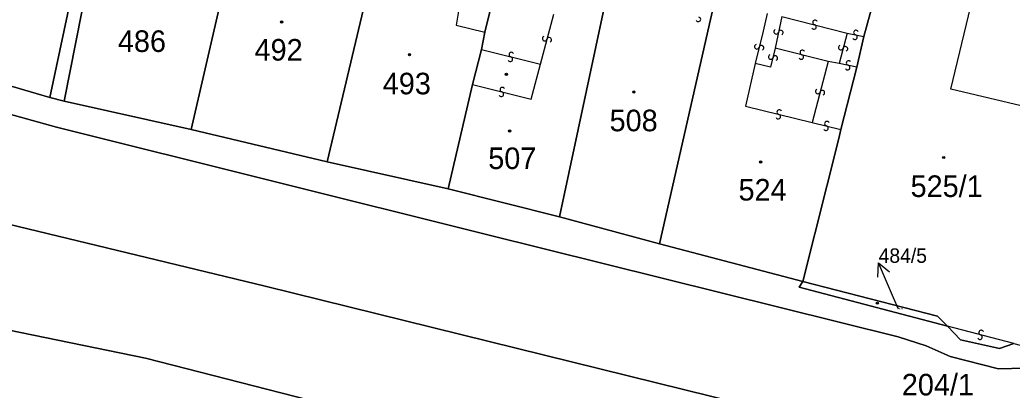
# Model space of a CAD drawing. Extents: x -600309 to -598967, y -1161267 to -1160292.
# Drawn here: x -599978 to -599899.7, y -1161164 to -1161134.8 of the extents above; entities that cross this region are included whole.
import ezdxf

# ---------------------------------------------------------------- set-up
doc = ezdxf.new("R2010")
doc.units = 0
for name, color, linetype in [('Level 1', 7, 'Continuous'), ('Level 13', 7, 'Continuous'), ('Level 3', 7, 'Continuous'), ('Level 4', 7, 'Continuous'), ('Level 5', 7, 'Continuous'), ('Level 57', 7, 'Continuous'), ('Level 60', 7, 'Continuous'), ('Vrstva 60', 7, 'Continuous')]:
    doc.layers.add(name, color=color, linetype=linetype)

msp = doc.modelspace()

# ---------------------------------------------------------------- linework, layer by layer
at = {"layer": 'Level 1'}
for points in [[(-600308.541, -1161016.585), (-600293.63, -1161026), (-600269.66, -1161037.42), (-600029.19, -1161135.15), (-600013.53, -1161140.37), (-599983.56, -1161149.75), (-599958.61, -1161155.76), (-599866.12, -1161178.6), (-599796.72, -1161205.03)], [(-600308.541, -1161029.185), (-600296.3, -1161037.15), (-600274.49, -1161049.84), (-600189.74, -1161080.33), (-600110.03, -1161111.48), (-600017.61, -1161148.92), (-599998.66, -1161155.17), (-599968.04, -1161161.44), (-599947.72, -1161166.65), (-599940.7, -1161168.31), (-599932.71, -1161170.39), (-599873.45, -1161186.23), (-599868.39, -1161187.94)], [(-600061.36, -1161110.25), (-600061.66, -1161110.46), (-600061.42, -1161112.61), (-600060.19, -1161113.93), (-600035.23, -1161124.14), (-600027.25, -1161127.68), (-600022.21, -1161129.09), (-599992.6, -1161138.37), (-599975.05, -1161143.25), (-599941.16, -1161151.69), (-599908.68, -1161159.77), (-599906.46, -1161160.46), (-599904.58, -1161161.31), (-599900.76, -1161162.29), (-599898.7, -1161162.24), (-599865.5, -1161170.1), (-599818.82, -1161185.87), (-599739.03, -1161205.3), (-599702.32, -1161201.68)], [(-599699.51, -1161214.79), (-599702.32, -1161201.68), (-599739.03, -1161205.3), (-599818.82, -1161185.87), (-599865.5, -1161170.1), (-599898.7, -1161162.24), (-599900.76, -1161162.29), (-599904.58, -1161161.31), (-599906.46, -1161160.46), (-599908.68, -1161159.77), (-599941.16, -1161151.69), (-599975.05, -1161143.25), (-599992.6, -1161138.37), (-600022.21, -1161129.09), (-600027.25, -1161127.68), (-600035.23, -1161124.14), (-600060.19, -1161113.93), (-600061.42, -1161112.61), (-600061.66, -1161110.46)], [(-599972.01, -1161124.1), (-599975.6, -1161140.9)], [(-599974.46, -1161141.2), (-599972.15, -1161129.47)], [(-599950.24, -1161131.34), (-599953.72, -1161145.96)], [(-599940.21, -1161131.34), (-599941.27, -1161135.74)], [(-599961.76, -1161131.79), (-599964.45, -1161143.41)], [(-599911.39, -1161136.1), (-599910.6, -1161133.23), (-599910.23, -1161131.71)], [(-599931.8, -1161133.46), (-599935.38, -1161150.31)], [(-599923.48, -1161134.76), (-599927.51, -1161152.42)], [(-599941.27, -1161135.74), (-599941.55, -1161137.12)], [(-599911.39, -1161136.1), (-599911.93, -1161138.5)], [(-599941.55, -1161137.12), (-599942.26, -1161139.88)], [(-599975.6, -1161140.9), (-599983.06, -1161138.73)], [(-599911.93, -1161138.5), (-599913.21, -1161143.41)], [(-599942.26, -1161139.88), (-599944.17, -1161148.1)], [(-599975.6, -1161140.9), (-599974.46, -1161141.2)], [(-599974.46, -1161141.2), (-599964.45, -1161143.41)], [(-599964.45, -1161143.41), (-599953.72, -1161145.96)], [(-599913.21, -1161143.41), (-599913.35, -1161144.14), (-599916.19, -1161155.41)], [(-599953.72, -1161145.96), (-599944.17, -1161148.1)], [(-599944.17, -1161148.1), (-599935.38, -1161150.31)], [(-599935.38, -1161150.31), (-599927.51, -1161152.42)], [(-599927.51, -1161152.42), (-599916.19, -1161155.41)], [(-599904.8, -1161158.92), (-599916.48, -1161155.86), (-599916.19, -1161155.41)], [(-599904.8, -1161158.92), (-599905.57, -1161158.12), (-599916.19, -1161155.41)], [(-599904.8, -1161158.92), (-599903.77, -1161159.99), (-599900.68, -1161160.69), (-599899.56, -1161160.29)]]:
    msp.add_lwpolyline(points, dxfattribs=at)
at = {"layer": 'Level 13'}
for centre, start, end in [((-599924.441, -1161134.74), 204.67281, 77.26281), ((-599915.326, -1161135.338), 202.91321, 75.50321), ((-599915.233, -1161134.982), 23.12767, 255.22566), ((-599936.558, -1161136.261), 112.45037, 344.54836), ((-599918.3, -1161135.712), 115.58309, 348.17309), ((-599917.94, -1161135.789), 295.79754, 167.89554), ((-599912.089, -1161136.14), 205.09339, 77.68339), ((-599912.01, -1161135.78), 25.30785, 257.40585), ((-599936.202, -1161136.358), 292.23591, 164.82591), ((-599919.819, -1161136.895), 113.33287, 345.92287), ((-599919.461, -1161136.986), 293.54733, 165.64533), ((-599913.198, -1161136.972), 112.44997, 345.03998), ((-599912.842, -1161137.068), 292.66443, 164.76243), ((-599939.275, -1161137.878), 203.15103, 75.74103), ((-599939.184, -1161137.521), 23.36549, 255.46348), ((-599918.729, -1161137.705), 113.39019, 345.98019), ((-599918.371, -1161137.796), 293.60464, 165.70264), ((-599916.327, -1161137.708), 203.11041, 75.20841), ((-599916.234, -1161137.352), 22.89595, 255.48595), ((-599912.668, -1161138.541), 206.0628, 78.1608), ((-599912.593, -1161138.18), 25.84834, 258.43834), ((-599939.985, -1161140.638), 203.23831, 75.82831), ((-599939.894, -1161140.281), 23.45277, 255.55076), ((-599915.018, -1161140.422), 112.36782, 344.95782), ((-599914.662, -1161140.519), 292.58228, 164.68027), ((-599918.145, -1161142.409), 203.35338, 75.94338), ((-599918.054, -1161142.051), 23.56783, 255.66583), ((-599914.384, -1161143.319), 203.72009, 76.31009), ((-599914.295, -1161142.961), 23.93454, 256.03254), ((-599902.228, -1161159.778), 202.72071, 74.8187), ((-599902.133, -1161159.422), 22.50625, 255.09625)]:
    msp.add_arc(centre, 0.184, start, end, dxfattribs=at)
at = {"layer": 'Level 3'}
for points in [[(-599895.98, -1161142.27), (-599904.52, -1161140.25), (-599900.84, -1161124.95), (-599908.11, -1161123.2)], [(-599947.54, -1161131.96), (-599943.17, -1161132.97), (-599943.55, -1161135.2), (-599941.27, -1161135.74)], [(-599936.9, -1161138.28), (-599935.85, -1161134.34)], [(-599919, -1161134.28), (-599919.32, -1161135.66), (-599919.95, -1161138.22)], [(-599917.86, -1161134.51), (-599918.37, -1161137)], [(-599917.86, -1161134.51), (-599912.7, -1161135.82)], [(-599912.7, -1161135.82), (-599913.33, -1161138.22)], [(-599912.7, -1161135.82), (-599911.39, -1161136.1)], [(-599941.55, -1161137.12), (-599936.9, -1161138.28)], [(-599918.37, -1161137), (-599918.74, -1161138.51), (-599919.95, -1161138.22)], [(-599914.2, -1161138.06), (-599918.37, -1161137)], [(-599942.26, -1161139.88), (-599937.62, -1161141.03), (-599936.9, -1161138.28)], [(-599919.95, -1161138.22), (-599920.72, -1161141.58), (-599915.47, -1161142.87)], [(-599914.2, -1161138.06), (-599915.47, -1161142.87)], [(-599913.33, -1161138.22), (-599914.2, -1161138.06)], [(-599911.93, -1161138.5), (-599913.33, -1161138.22)], [(-599915.47, -1161142.87), (-599913.21, -1161143.41)], [(-599899.56, -1161160.29), (-599904.8, -1161158.92)]]:
    msp.add_lwpolyline(points, dxfattribs=at)
at = {"layer": 'Level 5'}
for centre, radius in [((-599957.31, -1161134.96), 0.09), ((-599957.31, -1161134.96), 0.0521), ((-599947.22, -1161137.52), 0.09), ((-599947.22, -1161137.52), 0.0521), ((-599939.58, -1161139.07), 0.09), ((-599939.58, -1161139.07), 0.0521), ((-599929.53, -1161140.47), 0.09), ((-599929.53, -1161140.47), 0.0521), ((-599939.33, -1161143.55), 0.09), ((-599939.33, -1161143.55), 0.0521), ((-599905.09, -1161145.63), 0.09), ((-599919.53, -1161145.99), 0.09), ((-599919.53, -1161145.99), 0.0521), ((-599905.09, -1161145.63), 0.0521), ((-599910.32, -1161157.11), 0.09), ((-599910.32, -1161157.11), 0.0521)]:
    msp.add_circle(centre, radius, dxfattribs=at)
at = {"layer": 'Level 57'}
for p, q in [((-599909.038, -1161156.686), (-599910.222, -1161153.93)), ((-599908.65, -1161157.59), (-599909.038, -1161156.686))]:
    msp.add_line(p, q, dxfattribs=at)
msp.add_lwpolyline([(-599910.287, -1161155.046), (-599910.222, -1161153.93), (-599909.368, -1161154.651)], dxfattribs=at)
at = {"layer": 'Level 60'}
for points in [[(-599964.29, -1161091.77), (-599963.46, -1161088.64), (-599962.71, -1161088.89), (-599967.23, -1161108.7), (-599970.16, -1161120.49), (-599970.98, -1161124), (-599972.15, -1161129.47), (-599974.46, -1161141.2), (-599975.6, -1161140.9), (-599972.01, -1161124.1), (-599968.28, -1161108.43), (-599964.52, -1161092.68)], [(-599967.23, -1161108.7), (-599966.28, -1161108.94), (-599965.44, -1161110.41), (-599959.06, -1161118.34), (-599958.82, -1161118.75), (-599958.38, -1161118.83), (-599958.46, -1161119.23), (-599958.91, -1161119.12), (-599959.8, -1161123.12), (-599959.35, -1161123.22), (-599959.49, -1161123.75), (-599959.92, -1161123.65), (-599960.62, -1161126.63), (-599960.14, -1161126.72), (-599960.26, -1161127.21), (-599960.67, -1161127.13), (-599960.95, -1161128.23), (-599960.98, -1161128.38), (-599961.76, -1161131.79), (-599964.45, -1161143.41), (-599974.46, -1161141.2), (-599972.15, -1161129.47), (-599970.98, -1161124), (-599970.16, -1161120.49)], [(-599978.65, -1161121.98), (-599977.42, -1161117.01), (-599976.16, -1161111.75), (-599975.49, -1161109.01), (-599971, -1161110.27), (-599971.7, -1161113.1), (-599971.52, -1161113.15), (-599974.06, -1161123.59), (-599972.01, -1161124.1), (-599975.6, -1161140.9), (-599983.06, -1161138.73), (-599979.39, -1161124.2), (-599978.98, -1161122.5), (-599978.85, -1161121.95)], [(-599949.96, -1161130.04), (-599949.34, -1161127.15), (-599949.1, -1161127.24), (-599946.52, -1161127.87), (-599939.84, -1161129.57), (-599939.96, -1161129.87), (-599940.21, -1161131.34), (-599941.27, -1161135.74), (-599941.55, -1161137.12), (-599942.26, -1161139.88), (-599944.17, -1161148.1), (-599953.72, -1161145.96), (-599950.24, -1161131.34), (-599950.16, -1161130.94)], [(-599931.65, -1161133.02), (-599930.5, -1161127.7), (-599923.86, -1161128.98), (-599923.39, -1161126.91), (-599922, -1161127.2), (-599921.73, -1161127.26), (-599923.13, -1161133.27), (-599923.48, -1161134.76), (-599927.51, -1161152.42), (-599935.38, -1161150.31), (-599931.8, -1161133.46)], [(-599923.48, -1161134.76), (-599923.13, -1161133.27), (-599921.71, -1161133.58), (-599921.41, -1161132.37), (-599920.7, -1161129.42), (-599920.45, -1161128.25), (-599914.84, -1161129.61), (-599914.56, -1161129.69), (-599912.12, -1161130.24), (-599912.26, -1161130.98), (-599910.16, -1161131.42), (-599910.23, -1161131.71), (-599910.6, -1161133.23), (-599911.39, -1161136.1), (-599911.93, -1161138.5), (-599913.21, -1161143.41), (-599913.35, -1161144.14), (-599916.19, -1161155.41), (-599927.51, -1161152.42)], [(-599941.27, -1161135.74), (-599940.21, -1161131.34), (-599936.67, -1161132.28), (-599935.38, -1161132.59), (-599932.04, -1161133.38), (-599931.8, -1161133.46), (-599935.38, -1161150.31), (-599944.17, -1161148.1), (-599942.26, -1161139.88), (-599941.55, -1161137.12)], [(-599904.8, -1161158.92), (-599916.48, -1161155.86), (-599916.19, -1161155.41), (-599905.57, -1161158.12)]]:
    msp.add_lwpolyline(points, close=True, dxfattribs=at)
for points in [[(-599899.56, -1161160.29), (-599900.68, -1161160.69), (-599903.77, -1161159.99), (-599904.8, -1161158.92), (-599905.57, -1161158.12), (-599916.19, -1161155.41), (-599913.35, -1161144.14), (-599913.21, -1161143.41), (-599911.93, -1161138.5), (-599911.39, -1161136.1), (-599910.6, -1161133.23), (-599910.23, -1161131.71), (-599910.16, -1161131.42), (-599908.86, -1161126.11), (-599908.11, -1161123.2), (-599903.65, -1161105.17), (-599887.6, -1161109.7)], [(-599950.24, -1161131.34), (-599953.72, -1161145.96), (-599964.45, -1161143.41), (-599961.76, -1161131.79)], [(-599739.03, -1161205.3), (-599818.82, -1161185.87), (-599865.5, -1161170.1), (-599898.7, -1161162.24), (-599900.76, -1161162.29), (-599904.58, -1161161.31), (-599906.46, -1161160.46), (-599908.68, -1161159.77), (-599941.16, -1161151.69), (-599975.05, -1161143.25), (-599992.6, -1161138.37)], [(-599983.06, -1161138.73), (-599975.6, -1161140.9), (-599974.46, -1161141.2), (-599964.45, -1161143.41), (-599953.72, -1161145.96), (-599944.17, -1161148.1), (-599935.38, -1161150.31), (-599927.51, -1161152.42), (-599916.19, -1161155.41), (-599916.48, -1161155.86), (-599904.8, -1161158.92), (-599903.77, -1161159.99), (-599900.68, -1161160.69), (-599899.56, -1161160.29), (-599886.87, -1161163.62), (-599886.56, -1161162.52), (-599880.83, -1161163.77), (-599880.91, -1161164.07)]]:
    msp.add_lwpolyline(points, dxfattribs=at)
at = {"layer": 'Vrstva 60'}
for points in [[(-599745.25, -1161219.88), (-599778.44, -1161210.97), (-599796.72, -1161205.03), (-599866.12, -1161178.6), (-599958.61, -1161155.76), (-599983.56, -1161149.75), (-600013.53, -1161140.37), (-600029.19, -1161135.15), (-600269.66, -1161037.42)], [(-600269.66, -1161037.42), (-600029.19, -1161135.15), (-600013.53, -1161140.37), (-599983.56, -1161149.75), (-599958.61, -1161155.76), (-599866.12, -1161178.6), (-599796.72, -1161205.03), (-599778.44, -1161210.97), (-599745.25, -1161219.88)], [(-600189.74, -1161080.33), (-600110.03, -1161111.48), (-600017.61, -1161148.92), (-599998.66, -1161155.17), (-599968.04, -1161161.44), (-599947.72, -1161166.65), (-599940.7, -1161168.31), (-599932.71, -1161170.39), (-599873.45, -1161186.23), (-599868.39, -1161187.94), (-599854.87, -1161193.03), (-599799.36, -1161212.78), (-599792.54, -1161213.92), (-599784.84, -1161216.05), (-599772.79, -1161219.97)], [(-599772.79, -1161219.97), (-599784.84, -1161216.05), (-599792.54, -1161213.92), (-599799.36, -1161212.78), (-599854.87, -1161193.03), (-599868.39, -1161187.94), (-599873.45, -1161186.23), (-599932.71, -1161170.39), (-599940.7, -1161168.31), (-599947.72, -1161166.65), (-599968.04, -1161161.44), (-599998.66, -1161155.17), (-600017.61, -1161148.92), (-600110.03, -1161111.48), (-600189.74, -1161080.33)], [(-599739.03, -1161205.3), (-599818.82, -1161185.87), (-599865.5, -1161170.1), (-599898.7, -1161162.24), (-599900.76, -1161162.29), (-599904.58, -1161161.31), (-599906.46, -1161160.46), (-599908.68, -1161159.77), (-599941.16, -1161151.69), (-599975.05, -1161143.25), (-599992.6, -1161138.37)]]:
    msp.add_lwpolyline(points, dxfattribs=at)

# ---------------------------------------------------------------- texts
at = {"layer": 'Level 4'}
for s, height, p in [('486', 1.7, (-599970.22, -1161137.31)), ('492', 1.7, (-599959.44, -1161137.99)), ('493', 1.7, (-599949.33, -1161140.65)), ('508', 1.7, (-599931.44, -1161143.56)), ('507', 1.7, (-599941.01, -1161146.54)), ('525/1', 1.7, (-599907.7, -1161148.74)), ('524', 1.7, (-599921.27, -1161149.02)), ('484/5', 0.1, (-599908.65, -1161157.59))]:
    msp.add_text(s, height=height, dxfattribs=at).set_placement(p)
at = {"layer": 'Level 57'}
for s, height, p in [('484/5', 1.14, (-599910.223, -1161153.93)), ('204/1', 1.7, (-599908.39, -1161164.38))]:
    msp.add_text(s, height=height, dxfattribs=at).set_placement(p)

doc.saveas('drawing.dxf')
